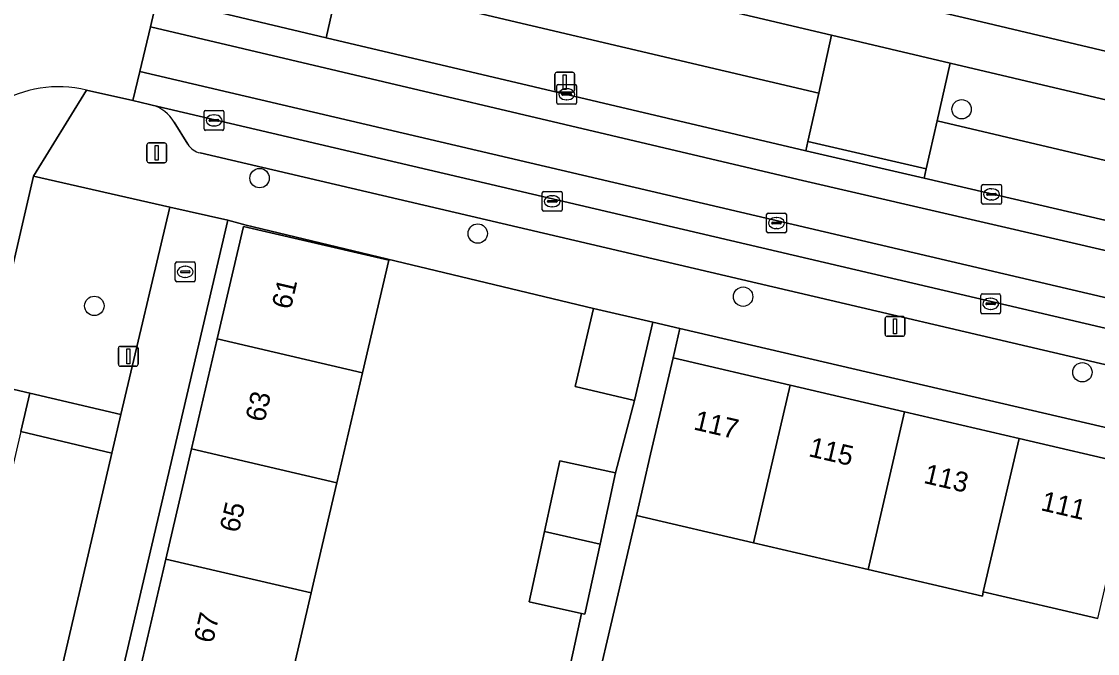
# Model space of a CAD drawing. Extents: x 163683 to 164494, y 382709 to 383872.
# Drawn here: x 163821.3 to 163875.6, y 383395.6 to 383427.4 of the extents above; entities that cross this region are included whole.
import ezdxf

# ---------------------------------------------------------------- set-up
doc = ezdxf.new("R2010")
doc.units = 0
for name, color, linetype in [('IMGEO_Boom', 7, 'Continuous'), ('IMGEO_Brandkraan', 7, 'Continuous'), ('IMGEO_Erf', 7, 'Continuous'), ('IMGEO_Groenvoorziening', 7, 'Continuous'), ('IMGEO_Kolk', 7, 'Continuous'), ('IMGEO_Lichtmast', 7, 'Continuous'), ('IMGEO_Muur', 7, 'Continuous'), ('IMGEO_Pand', 7, 'Continuous'), ('IMGEO_Pand_nummerreeks', 7, 'Continuous'), ('IMGEO_Parkeervlak_open', 7, 'Continuous'), ('IMGEO_Rijbaan_lokaal_open', 7, 'Continuous'), ('IMGEO_Rioolput', 7, 'Continuous'), ('IMGEO_Voetpad_open', 7, 'Continuous')]:
    doc.layers.add(name, color=color, linetype=linetype)

msp = doc.modelspace()

# ---------------------------------------------------------------- linework, layer by layer
at = {"layer": 'IMGEO_Boom'}
for centre in [(163868.779, 383423.003), (163833.36, 383419.53), (163844.366, 383416.735), (163857.755, 383413.552), (163825.023, 383413.087), (163874.871, 383409.739)]:
    msp.add_circle(centre, 0.489, dxfattribs=at)
at = {"layer": 'IMGEO_Brandkraan'}
for p, q in [((163829.109, 383414.38), (163829.109, 383415.232)), ((163829.184, 383415.306), (163830.036, 383415.306)), ((163829.368, 383414.8), (163829.368, 383414.812)), ((163829.411, 383414.849), (163829.809, 383414.849)), ((163829.597, 383415.086), (163829.622, 383415.086)), ((163829.852, 383414.812), (163829.852, 383414.8)), ((163830.11, 383415.232), (163830.11, 383414.38)), ((163830.036, 383414.306), (163829.184, 383414.306)), ((163829.806, 383414.763), (163829.408, 383414.763)), ((163829.62, 383414.526), (163829.595, 383414.526))]:
    msp.add_line(p, q, dxfattribs=at)
for points in [[(163829.109, 383414.38), (163829.109, 383415.232)], [(163829.184, 383415.306), (163830.036, 383415.306)], [(163830.11, 383415.232), (163830.11, 383414.38)], [(163830.036, 383414.306), (163829.184, 383414.306)]]:
    msp.add_lwpolyline(points, dxfattribs=at)
for centre, radius, start, end in [((163829.186, 383415.23), 0.0765, 91.552, 178.448), ((163829.186, 383415.23), 0.0765, 91.552, 178.448), ((163829.408, 383414.809), 0.0403, 85.8775, 175.7526), ((163829.405, 383414.799), 0.0366, 178.938, 274.7102), ((163829.809, 383414.806), 0.043, 264.8664, 352.4533), ((163829.813, 383414.811), 0.0386, 1.7309, 96.639), ((163830.034, 383415.23), 0.0765, 1.552, 88.448), ((163830.034, 383415.23), 0.0765, 1.552, 88.448), ((163829.186, 383414.382), 0.0765, 181.552, 268.448), ((163829.186, 383414.382), 0.0765, 181.552, 268.448), ((163830.034, 383414.382), 0.0765, 271.552, 358.448), ((163830.034, 383414.382), 0.0765, 271.552, 358.448)]:
    msp.add_arc(centre, radius, start, end, dxfattribs=at)
for centre, major_axis, ratio, start_param, end_param in [((163829.596, 383414.806), (-0.387, 0.002), 0.722429, 4.712389, 7.853982), ((163829.621, 383414.806), (-0.39, 0.002), 0.717154, 1.570796, 4.712389)]:
    msp.add_ellipse(centre, major_axis=major_axis, ratio=ratio, start_param=start_param, end_param=end_param, dxfattribs=at)
at = {"layer": 'IMGEO_Erf'}
for points in [[(163837.368, 383461.967), (163835.189, 383452.678), (163834.16, 383448.296), (163833.754, 383446.531), (163831.477, 383436.455), (163837.936, 383434.797), (163843.936, 383433.408), (163866.249, 383428.241), (163868.851, 383427.627), (163899.759, 383420.325), (163906.853, 383459.8)], [(163848.732, 383393.559), (163849.609, 383397.58), (163846.961, 383398.157), (163847.737, 383401.717), (163848.512, 383405.276), (163851.324, 383404.664), (163852.278, 383408.324), (163849.282, 383409.023), (163850.201, 383412.963), (163832.675, 383417.164), (163831.753, 383417.404), (163823.913, 383383.838)], [(163827.337, 383394.767), (163828.633, 383400.319), (163829.929, 383405.872), (163831.226, 383411.426), (163832.55, 383417.097), (163839.879, 383415.386), (163838.555, 383409.716), (163837.258, 383404.162), (163836.337, 383400.216), (163835.962, 383398.609), (163834.665, 383393.056)], [(163875.643, 383397.326), (163873.353, 383397.858), (163869.873, 383398.666), (163869.824, 383398.456), (163864.056, 383399.797), (163858.287, 383401.139), (163852.37, 383402.515), (163849.168, 383388.794)]]:
    msp.add_lwpolyline(points, dxfattribs=at)
msp.add_lwpolyline([(163854.563, 383411.946), (163854.218, 383410.461), (163860.136, 383409.085), (163865.905, 383407.744), (163871.674, 383406.403), (163877.443, 383405.061), (163883.212, 383403.72), (163888.982, 383402.379), (163894.751, 383401.037), (163900.52, 383399.696), (163906.435, 383398.321), (163906.774, 383399.807)], close=True, dxfattribs=at)
at = {"layer": 'IMGEO_Groenvoorziening'}
for points in [[(163829.425, 383428.331), (163836.716, 383426.613), (163837.373, 383429.512), (163838.037, 383432.437), (163830.795, 383434.141)], [(163861.569, 383423.819), (163862.222, 383426.748), (163838.037, 383432.437), (163837.373, 383429.512)], [(163861.025, 383421.375), (163861.569, 383423.819), (163837.373, 383429.512), (163836.716, 383426.613), (163860.921, 383420.912)], [(163868.201, 383425.328), (163867.54, 383422.415), (163890.603, 383416.989), (163891.265, 383419.907)], [(163866.886, 383419.533), (163889.964, 383414.169), (163890.603, 383416.989), (163867.54, 383422.415), (163866.991, 383419.994)], [(163828.831, 383418.072), (163821.949, 383419.635), (163819.527, 383409.206), (163821.765, 383408.682), (163826.362, 383407.605)], [(163814.878, 383379.041), (163820.129, 383380.9), (163825.91, 383405.656), (163821.317, 383406.754)]]:
    msp.add_lwpolyline(points, close=True, dxfattribs=at)
at = {"layer": 'IMGEO_Kolk'}
for p, q in [((163848.355, 383423.333), (163848.355, 383424.185)), ((163848.43, 383424.259), (163849.282, 383424.259)), ((163848.843, 383424.039), (163848.868, 383424.039)), ((163849.356, 383424.185), (163849.356, 383423.333)), ((163848.614, 383423.753), (163848.614, 383423.765)), ((163849.052, 383423.716), (163848.654, 383423.716)), ((163848.657, 383423.802), (163849.055, 383423.802)), ((163849.098, 383423.765), (163849.098, 383423.753)), ((163830.637, 383422.942), (163831.489, 383422.942)), ((163849.282, 383423.259), (163848.43, 383423.259)), ((163848.866, 383423.479), (163848.841, 383423.479)), ((163830.562, 383422.016), (163830.562, 383422.868)), ((163830.821, 383422.436), (163830.821, 383422.448)), ((163831.259, 383422.399), (163830.861, 383422.399)), ((163830.864, 383422.485), (163831.262, 383422.485)), ((163831.05, 383422.722), (163831.075, 383422.722)), ((163831.305, 383422.448), (163831.305, 383422.436)), ((163831.563, 383422.868), (163831.563, 383422.016)), ((163831.489, 383421.942), (163830.637, 383421.942)), ((163831.073, 383422.162), (163831.048, 383422.162)), ((163869.787, 383418.287), (163869.787, 383419.139)), ((163869.862, 383419.213), (163870.714, 383419.213)), ((163870.788, 383419.139), (163870.788, 383418.287)), ((163847.624, 383417.937), (163847.624, 383418.789)), ((163847.699, 383418.863), (163848.551, 383418.863)), ((163848.112, 383418.643), (163848.137, 383418.643)), ((163848.625, 383418.789), (163848.625, 383417.937)), ((163870.046, 383418.707), (163870.046, 383418.719)), ((163870.484, 383418.67), (163870.086, 383418.67)), ((163870.089, 383418.756), (163870.487, 383418.756)), ((163870.275, 383418.993), (163870.3, 383418.993)), ((163870.53, 383418.719), (163870.53, 383418.707)), ((163847.883, 383418.357), (163847.883, 383418.369)), ((163848.321, 383418.32), (163847.923, 383418.32)), ((163847.926, 383418.406), (163848.324, 383418.406)), ((163848.135, 383418.083), (163848.11, 383418.083)), ((163848.367, 383418.369), (163848.367, 383418.357)), ((163870.714, 383418.213), (163869.862, 383418.213)), ((163870.298, 383418.433), (163870.273, 383418.433)), ((163848.551, 383417.863), (163847.699, 383417.863)), ((163869.744, 383412.767), (163869.744, 383413.619)), ((163869.819, 383413.693), (163870.671, 383413.693)), ((163870.003, 383413.187), (163870.003, 383413.199)), ((163870.046, 383413.236), (163870.444, 383413.236)), ((163870.232, 383413.473), (163870.257, 383413.473)), ((163870.487, 383413.199), (163870.487, 383413.187)), ((163870.745, 383413.619), (163870.745, 383412.767)), ((163870.671, 383412.693), (163869.819, 383412.693)), ((163870.441, 383413.15), (163870.043, 383413.15)), ((163870.255, 383412.913), (163870.23, 383412.913))]:
    msp.add_line(p, q, dxfattribs=at)
for points in [[(163848.355, 383423.333), (163848.355, 383424.185)], [(163848.43, 383424.259), (163849.282, 383424.259)], [(163849.356, 383424.185), (163849.356, 383423.333)], [(163830.637, 383422.942), (163831.489, 383422.942)], [(163849.282, 383423.259), (163848.43, 383423.259)], [(163830.562, 383422.016), (163830.562, 383422.868)], [(163831.563, 383422.868), (163831.563, 383422.016)], [(163831.489, 383421.942), (163830.637, 383421.942)], [(163869.787, 383418.287), (163869.787, 383419.139)], [(163869.862, 383419.213), (163870.714, 383419.213)], [(163870.788, 383419.139), (163870.788, 383418.287)], [(163847.624, 383417.937), (163847.624, 383418.789)], [(163847.699, 383418.863), (163848.551, 383418.863)], [(163848.625, 383418.789), (163848.625, 383417.937)], [(163870.714, 383418.213), (163869.862, 383418.213)], [(163848.551, 383417.863), (163847.699, 383417.863)], [(163869.744, 383412.767), (163869.744, 383413.619)], [(163869.819, 383413.693), (163870.671, 383413.693)], [(163870.745, 383413.619), (163870.745, 383412.767)], [(163870.671, 383412.693), (163869.819, 383412.693)]]:
    msp.add_lwpolyline(points, dxfattribs=at)
for centre, radius, start, end in [((163848.432, 383424.183), 0.0765, 91.552, 178.448), ((163848.432, 383424.183), 0.0765, 91.552, 178.448), ((163849.28, 383424.183), 0.0765, 1.552, 88.448), ((163849.28, 383424.183), 0.0765, 1.552, 88.448), ((163848.654, 383423.762), 0.0403, 85.8775, 175.7526), ((163848.651, 383423.752), 0.0366, 178.938, 274.7102), ((163849.055, 383423.759), 0.043, 264.8664, 352.4533), ((163849.059, 383423.764), 0.0386, 1.7309, 96.639), ((163830.639, 383422.866), 0.0765, 91.552, 178.448), ((163830.639, 383422.866), 0.0765, 91.552, 178.448), ((163831.487, 383422.866), 0.0765, 1.552, 88.448), ((163831.487, 383422.866), 0.0765, 1.552, 88.448), ((163848.432, 383423.335), 0.0765, 181.552, 268.448), ((163848.432, 383423.335), 0.0765, 181.552, 268.448), ((163849.28, 383423.335), 0.0765, 271.552, 358.448), ((163849.28, 383423.335), 0.0765, 271.552, 358.448), ((163830.861, 383422.445), 0.0403, 85.8775, 175.7526), ((163830.858, 383422.435), 0.0366, 178.938, 274.7102), ((163831.262, 383422.442), 0.043, 264.8664, 352.4533), ((163831.266, 383422.447), 0.0386, 1.7309, 96.639), ((163830.639, 383422.018), 0.0765, 181.552, 268.448), ((163830.639, 383422.018), 0.0765, 181.552, 268.448), ((163831.487, 383422.018), 0.0765, 271.552, 358.448), ((163831.487, 383422.018), 0.0765, 271.552, 358.448), ((163869.864, 383419.137), 0.0765, 91.552, 178.448), ((163869.864, 383419.137), 0.0765, 91.552, 178.448), ((163870.712, 383419.137), 0.0765, 1.552, 88.448), ((163870.712, 383419.137), 0.0765, 1.552, 88.448), ((163847.701, 383418.787), 0.0765, 91.552, 178.448), ((163847.701, 383418.787), 0.0765, 91.552, 178.448), ((163848.549, 383418.787), 0.0765, 1.552, 88.448), ((163848.549, 383418.787), 0.0765, 1.552, 88.448), ((163870.086, 383418.716), 0.0403, 85.8775, 175.7526), ((163870.083, 383418.706), 0.0366, 178.938, 274.7102), ((163870.487, 383418.713), 0.043, 264.8664, 352.4533), ((163870.491, 383418.718), 0.0386, 1.7309, 96.639), ((163847.923, 383418.366), 0.0403, 85.8775, 175.7526), ((163847.92, 383418.356), 0.0366, 178.938, 274.7102), ((163848.324, 383418.363), 0.043, 264.8664, 352.4533), ((163848.328, 383418.368), 0.0386, 1.7309, 96.639), ((163869.864, 383418.289), 0.0765, 181.552, 268.448), ((163869.864, 383418.289), 0.0765, 181.552, 268.448), ((163870.712, 383418.289), 0.0765, 271.552, 358.448), ((163870.712, 383418.289), 0.0765, 271.552, 358.448), ((163847.701, 383417.939), 0.0765, 181.552, 268.448), ((163847.701, 383417.939), 0.0765, 181.552, 268.448), ((163848.549, 383417.939), 0.0765, 271.552, 358.448), ((163848.549, 383417.939), 0.0765, 271.552, 358.448), ((163869.821, 383413.617), 0.0765, 91.552, 178.448), ((163869.821, 383413.617), 0.0765, 91.552, 178.448), ((163870.043, 383413.196), 0.0403, 85.8775, 175.7526), ((163870.04, 383413.186), 0.0366, 178.938, 274.7102), ((163870.444, 383413.193), 0.043, 264.8664, 352.4533), ((163870.448, 383413.198), 0.0386, 1.7309, 96.639), ((163870.669, 383413.617), 0.0765, 1.552, 88.448), ((163870.669, 383413.617), 0.0765, 1.552, 88.448), ((163869.821, 383412.769), 0.0765, 181.552, 268.448), ((163869.821, 383412.769), 0.0765, 181.552, 268.448), ((163870.669, 383412.769), 0.0765, 271.552, 358.448), ((163870.669, 383412.769), 0.0765, 271.552, 358.448)]:
    msp.add_arc(centre, radius, start, end, dxfattribs=at)
for centre, major_axis, ratio, start_param, end_param in [((163848.842, 383423.759), (-0.387, 0.002), 0.722429, 4.712389, 7.853982), ((163848.867, 383423.759), (-0.39, 0.002), 0.717154, 1.570796, 4.712389), ((163831.049, 383422.442), (-0.387, 0.002), 0.722429, 4.712389, 7.853982), ((163831.074, 383422.442), (-0.39, 0.002), 0.717154, 1.570796, 4.712389), ((163848.111, 383418.363), (-0.387, 0.002), 0.722429, 4.712389, 7.853982), ((163848.136, 383418.363), (-0.39, 0.002), 0.717154, 1.570796, 4.712389), ((163870.274, 383418.713), (-0.387, 0.002), 0.722429, 4.712389, 7.853982), ((163870.299, 383418.713), (-0.39, 0.002), 0.717154, 1.570796, 4.712389), ((163870.231, 383413.193), (-0.387, 0.002), 0.722429, 4.712389, 7.853982), ((163870.256, 383413.193), (-0.39, 0.002), 0.717154, 1.570796, 4.712389)]:
    msp.add_ellipse(centre, major_axis=major_axis, ratio=ratio, start_param=start_param, end_param=end_param, dxfattribs=at)
at = {"layer": 'IMGEO_Lichtmast'}
for p, q in [((163848.26, 383423.968), (163848.26, 383424.768)), ((163848.26, 383424.768), (163848.26, 383423.968)), ((163848.36, 383424.868), (163849.15, 383424.868)), ((163849.15, 383424.868), (163848.36, 383424.868)), ((163849.25, 383424.768), (163849.25, 383423.968)), ((163849.25, 383423.968), (163849.25, 383424.768)), ((163849.15, 383423.868), (163848.36, 383423.868)), ((163848.36, 383423.868), (163849.15, 383423.868)), ((163827.674, 383420.404), (163827.674, 383421.204)), ((163827.674, 383421.204), (163827.674, 383420.404)), ((163827.774, 383421.304), (163828.564, 383421.304)), ((163828.564, 383421.304), (163827.774, 383421.304)), ((163828.664, 383421.204), (163828.664, 383420.404)), ((163828.664, 383420.404), (163828.664, 383421.204)), ((163828.564, 383420.304), (163827.774, 383420.304)), ((163827.774, 383420.304), (163828.564, 383420.304)), ((163864.922, 383411.654), (163864.922, 383412.454)), ((163864.922, 383412.454), (163864.922, 383411.654)), ((163865.022, 383412.554), (163865.812, 383412.554)), ((163865.812, 383412.554), (163865.022, 383412.554)), ((163865.912, 383412.454), (163865.912, 383411.654)), ((163865.912, 383411.654), (163865.912, 383412.454)), ((163865.812, 383411.554), (163865.022, 383411.554)), ((163865.022, 383411.554), (163865.812, 383411.554)), ((163826.337, 383411.048), (163827.127, 383411.048)), ((163827.127, 383411.048), (163826.337, 383411.048)), ((163826.237, 383410.148), (163826.237, 383410.948)), ((163826.237, 383410.948), (163826.237, 383410.148)), ((163827.227, 383410.948), (163827.227, 383410.148)), ((163827.227, 383410.148), (163827.227, 383410.948)), ((163827.127, 383410.048), (163826.337, 383410.048)), ((163826.337, 383410.048), (163827.127, 383410.048))]:
    msp.add_line(p, q, dxfattribs=at)
for points in [[(163848.68, 383424.743), (163848.83, 383424.743), (163848.83, 383423.993), (163848.68, 383423.993), (163848.68, 383424.743)], [(163828.094, 383421.179), (163828.244, 383421.179), (163828.244, 383420.429), (163828.094, 383420.429), (163828.094, 383421.179)], [(163865.342, 383412.429), (163865.492, 383412.429), (163865.492, 383411.679), (163865.342, 383411.679), (163865.342, 383412.429)], [(163826.657, 383410.923), (163826.807, 383410.923), (163826.807, 383410.173), (163826.657, 383410.173), (163826.657, 383410.923)]]:
    msp.add_lwpolyline(points, dxfattribs=at)
for centre, start, end in [((163848.36, 383424.768), 90, 180), ((163848.36, 383424.768), 90, 180), ((163849.15, 383424.768), 0, 90), ((163849.15, 383424.768), 360, 90), ((163848.36, 383423.968), 180, 270), ((163848.36, 383423.968), 180, 270), ((163849.15, 383423.968), 270, 0), ((163849.15, 383423.968), 270, 0), ((163827.774, 383421.204), 90, 180), ((163827.774, 383421.204), 90, 180), ((163828.564, 383421.204), 0, 90), ((163828.564, 383421.204), 360, 90), ((163827.774, 383420.404), 180, 270), ((163827.774, 383420.404), 180, 270), ((163828.564, 383420.404), 270, 0), ((163828.564, 383420.404), 270, 0), ((163865.022, 383412.454), 90, 180), ((163865.022, 383412.454), 90, 180), ((163865.812, 383412.454), 0, 90), ((163865.812, 383412.454), 360, 90), ((163865.022, 383411.654), 180, 270), ((163865.022, 383411.654), 180, 270), ((163865.812, 383411.654), 270, 0), ((163865.812, 383411.654), 270, 0), ((163826.337, 383410.948), 90, 180), ((163826.337, 383410.948), 90, 180), ((163827.127, 383410.948), 0, 90), ((163827.127, 383410.948), 360, 90), ((163826.337, 383410.148), 180, 270), ((163826.337, 383410.148), 180, 270), ((163827.127, 383410.148), 270, 0), ((163827.127, 383410.148), 270, 0)]:
    msp.add_arc(centre, 0.1, start, end, dxfattribs=at)
at = {"layer": 'IMGEO_Muur'}
msp.add_lwpolyline([(163832.675, 383417.164), (163850.201, 383412.963)], dxfattribs=at)
at = {"layer": 'IMGEO_Pand'}
for points in [[(163831.226, 383411.426), (163838.555, 383409.716), (163839.879, 383415.386), (163832.55, 383417.097)], [(163853.197, 383412.264), (163850.201, 383412.963), (163849.282, 383409.023), (163852.278, 383408.324)], [(163837.258, 383404.162), (163838.555, 383409.716), (163831.226, 383411.426), (163829.929, 383405.872)], [(163858.287, 383401.139), (163860.136, 383409.085), (163854.218, 383410.461), (163853.088, 383405.602), (163852.37, 383402.515)], [(163865.905, 383407.744), (163860.136, 383409.085), (163858.287, 383401.139), (163864.056, 383399.797)], [(163871.674, 383406.403), (163865.905, 383407.744), (163864.056, 383399.797), (163869.824, 383398.456), (163869.873, 383398.666)], [(163877.443, 383405.061), (163871.674, 383406.403), (163869.873, 383398.666), (163873.353, 383397.858), (163875.643, 383397.326)], [(163837.258, 383404.162), (163829.929, 383405.872), (163828.633, 383400.319), (163835.962, 383398.609), (163836.337, 383400.216)], [(163850.54, 383401.063), (163851.324, 383404.664), (163848.512, 383405.276), (163847.737, 383401.717)], [(163850.54, 383401.063), (163847.737, 383401.717), (163846.961, 383398.157), (163849.609, 383397.58), (163849.773, 383397.544)], [(163835.962, 383398.609), (163828.633, 383400.319), (163827.337, 383394.767), (163834.665, 383393.056)]]:
    msp.add_lwpolyline(points, close=True, dxfattribs=at)
at = {"layer": 'IMGEO_Parkeervlak_open'}
for points in [[(163830.362, 383420.809), (163903.102, 383403.799), (163903.557, 383405.524), (163891.83, 383408.274), (163827.942, 383423.215)], [(163829.045, 383422.353), (163829.744, 383421.252)]]:
    msp.add_lwpolyline(points, dxfattribs=at)
for centre, radius, start, end in [((163827.465, 383421.468), 1.811, 29.2564, 74.7279), ((163830.515, 383421.675), 0.879, 208.7508, 259.9811)]:
    msp.add_arc(centre, radius, start, end, dxfattribs=at)
at = {"layer": 'IMGEO_Rijbaan_lokaal_open'}
msp.add_lwpolyline([(163824.633, 383423.974), (163826.97, 383423.439), (163827.318, 383424.902), (163827.854, 383427.16), (163828.201, 383428.619), (163825.874, 383429.195)], dxfattribs=at)
for points in [[(163889.964, 383414.169), (163866.886, 383419.533), (163860.921, 383420.912), (163836.716, 383426.613), (163829.425, 383428.331), (163828.201, 383428.619), (163827.854, 383427.16), (163860.525, 383419.464), (163892.693, 383412.027), (163893.023, 383413.458)], [(163892.693, 383412.027), (163860.525, 383419.464), (163827.854, 383427.16), (163827.318, 383424.902), (163892.163, 383409.724)], [(163892.163, 383409.724), (163827.318, 383424.902), (163826.97, 383423.439), (163827.799, 383423.249), (163827.942, 383423.215), (163891.83, 383408.274)]]:
    msp.add_lwpolyline(points, close=True, dxfattribs=at)
msp.add_arc((163823.227, 383418.172), 5.97, 76.3823, 165.4748, dxfattribs=at)
at = {"layer": 'IMGEO_Rioolput'}
for p, q in [((163858.938, 383416.84), (163858.938, 383417.692)), ((163859.013, 383417.766), (163859.865, 383417.766)), ((163859.426, 383417.546), (163859.451, 383417.546)), ((163859.939, 383417.692), (163859.939, 383416.84)), ((163859.197, 383417.26), (163859.197, 383417.272)), ((163859.635, 383417.223), (163859.237, 383417.223)), ((163859.24, 383417.309), (163859.638, 383417.309)), ((163859.449, 383416.986), (163859.424, 383416.986)), ((163859.681, 383417.272), (163859.681, 383417.26)), ((163859.865, 383416.766), (163859.013, 383416.766))]:
    msp.add_line(p, q, dxfattribs=at)
for points in [[(163858.938, 383416.84), (163858.938, 383417.692)], [(163859.013, 383417.766), (163859.865, 383417.766)], [(163859.939, 383417.692), (163859.939, 383416.84)], [(163859.865, 383416.766), (163859.013, 383416.766)]]:
    msp.add_lwpolyline(points, dxfattribs=at)
for centre, radius, start, end in [((163859.015, 383417.69), 0.0765, 91.552, 178.448), ((163859.015, 383417.69), 0.0765, 91.552, 178.448), ((163859.863, 383417.69), 0.0765, 1.552, 88.448), ((163859.863, 383417.69), 0.0765, 1.552, 88.448), ((163859.237, 383417.269), 0.0403, 85.8775, 175.7526), ((163859.234, 383417.259), 0.0366, 178.938, 274.7102), ((163859.638, 383417.266), 0.043, 264.8664, 352.4533), ((163859.642, 383417.271), 0.0386, 1.7309, 96.639), ((163859.015, 383416.842), 0.0765, 181.552, 268.448), ((163859.015, 383416.842), 0.0765, 181.552, 268.448), ((163859.863, 383416.842), 0.0765, 271.552, 358.448), ((163859.863, 383416.842), 0.0765, 271.552, 358.448)]:
    msp.add_arc(centre, radius, start, end, dxfattribs=at)
for centre, major_axis, ratio, start_param, end_param in [((163859.425, 383417.266), (-0.387, 0.002), 0.722429, 4.712389, 7.853982), ((163859.45, 383417.266), (-0.39, 0.002), 0.717154, 1.570796, 4.712389)]:
    msp.add_ellipse(centre, major_axis=major_axis, ratio=ratio, start_param=start_param, end_param=end_param, dxfattribs=at)
at = {"layer": 'IMGEO_Voetpad_open'}
for points in [[(163868.851, 383427.627), (163866.249, 383428.241), (163843.936, 383433.408), (163837.936, 383434.797), (163831.477, 383436.455), (163829.014, 383437.037), (163825.874, 383429.195), (163828.201, 383428.619), (163829.425, 383428.331), (163830.795, 383434.141), (163838.037, 383432.437), (163862.222, 383426.748), (163868.201, 383425.328), (163891.265, 383419.907), (163899.366, 383418.003), (163899.759, 383420.325)], [(163868.201, 383425.328), (163862.222, 383426.748), (163861.569, 383423.819), (163861.025, 383421.375), (163866.991, 383419.994), (163867.54, 383422.415)], [(163866.886, 383419.533), (163866.991, 383419.994), (163861.025, 383421.375), (163860.921, 383420.912)], [(163831.753, 383417.404), (163828.831, 383418.072), (163826.362, 383407.605), (163825.91, 383405.656), (163820.129, 383380.9), (163819.453, 383378.12), (163817.093, 383368.037), (163821.142, 383367.099), (163821.737, 383369.782), (163822.759, 383374.155), (163821.542, 383374.44), (163822.253, 383377.486), (163823.745, 383383.877), (163823.913, 383383.838)], [(163826.362, 383407.605), (163821.765, 383408.682), (163821.317, 383406.754), (163825.91, 383405.656)]]:
    msp.add_lwpolyline(points, close=True, dxfattribs=at)
for points in [[(163821.317, 383406.754), (163821.765, 383408.682), (163819.527, 383409.206), (163821.949, 383419.635), (163824.633, 383423.974)], [(163827.942, 383423.215), (163827.799, 383423.249), (163826.97, 383423.439), (163824.633, 383423.974), (163821.949, 383419.635), (163828.831, 383418.072), (163831.753, 383417.404), (163832.675, 383417.164), (163850.201, 383412.963), (163853.197, 383412.264), (163854.563, 383411.946), (163906.774, 383399.807), (163908.678, 383400.897)], [(163829.744, 383421.252), (163829.045, 383422.353)], [(163905.911, 383403.137), (163903.102, 383403.799), (163830.362, 383420.809)], [(163849.168, 383388.794), (163852.37, 383402.515), (163853.088, 383405.602), (163854.218, 383410.461), (163854.563, 383411.946), (163853.197, 383412.264), (163852.278, 383408.324), (163851.324, 383404.664), (163850.54, 383401.063), (163849.773, 383397.544), (163849.609, 383397.58), (163848.732, 383393.559)]]:
    msp.add_lwpolyline(points, dxfattribs=at)
for centre, radius, start, end in [((163823.227, 383418.172), 5.97, 76.3823, 165.4748), ((163827.465, 383421.468), 1.811, 29.2564, 74.7279), ((163830.515, 383421.675), 0.879, 208.7508, 259.9811)]:
    msp.add_arc(centre, radius, start, end, dxfattribs=at)

# ---------------------------------------------------------------- texts
at = {"layer": 'IMGEO_Pand_nummerreeks'}
for s, rotation, p in [('61', 76.8586, (163834.931, 383412.869)), ('63', 76.8586, (163833.604, 383407.183)), ('117', 346.9117, (163855.212, 383406.863)), ('115', 346.9136, (163861.013, 383405.514)), ('113', 346.9136, (163866.815, 383404.165)), ('111', 346.9136, (163872.727, 383402.79)), ('65', 76.8586, (163832.302, 383401.607)), ('67', 76.8586, (163831, 383396.032))]:
    msp.add_text(s, height=1, rotation=rotation, dxfattribs=at).set_placement(p)

doc.saveas('drawing.dxf')
